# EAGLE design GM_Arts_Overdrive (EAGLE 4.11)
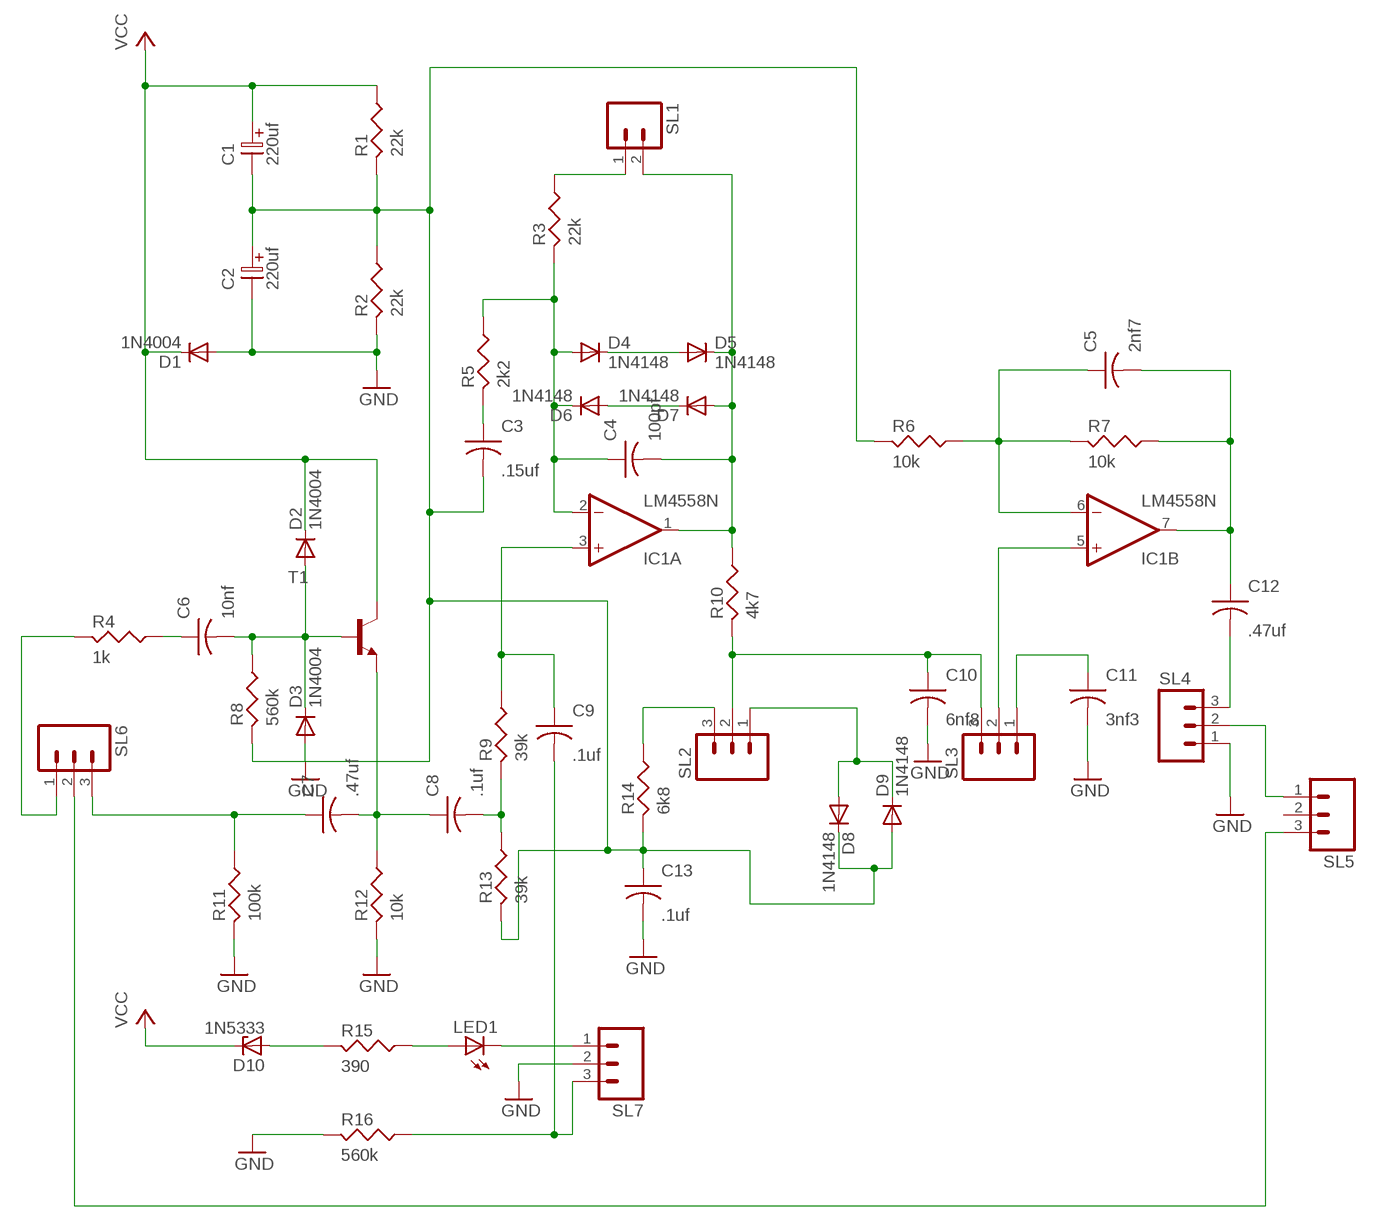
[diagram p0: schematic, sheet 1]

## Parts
C1  220uf  ELC-5L  [ES-5L]
C2  220uf  ELC-5L  [ES-5L]
C3  .15uf  CAP-5  [C-5]
C4  100pf  CAP-5  [C-5]
C5  2nf7  CAP-5  [C-5]
C6  10nf  CAP-5  [C-5]
C7  .47uf  CAP-7,5  [C-7,5]
C8  .1uf  CAP-5  [C-5]
C9  .1uf  CAP-5  [C-5]
C10  6nf8  CAP-7,5  [C-7,5]
C11  3nf3  CAP-5  [C-5]
C12  .47uf  CAP-7,5  [C-7,5]
C13  .1uf  CAP-5  [C-5]
D1  1N4004  [DO41-10]
D2  1N4004  [DO41-10]
D3  1N4004  [DO41-10]
D4  1N4148  [DO35-10]
D5  1N4148  [DO35-10]
D6  1N4148  [DO35-10]
D7  1N4148  [DO35-10]
D8  1N4148  [DO35-10]
D9  1N4148  [DO35-10]
D10  1N5333  [C1702-15]
IC1  LM4558N  [DIL08]
LED1  LED5MM  [LED5MM]
R1  22k  RESUS-12,5  [R-12,5]
R2  22k  RESUS-12,5  [R-12,5]
R3  22k  RESUS-12,5  [R-12,5]
R4  1k  RESUS-12,5  [R-12,5]
R5  2k2  RESUS-12,5  [R-12,5]
R6  10k  RESUS-12,5  [R-12,5]
R7  10k  RESUS-12,5  [R-12,5]
R8  560k  RESUS-12,5  [R-12,5]
R9  39k  RESUS-12,5  [R-12,5]
R10  4k7  RESUS-12,5  [R-12,5]
R11  100k  RESUS-12,5  [R-12,5]
R12  10k  RESUS-12,5  [R-12,5]
R13  39k  RESUS-12,5  [R-12,5]
R14  6k8  RESUS-12,5  [R-12,5]
R15  390  RESUS-12,5  [R-12,5]
R16  560k  RESUS-12,5  [R-12,5]
SL1  M02  [02P]
SL2  M03  [03P]
SL3  M03  [03P]
SL4  M03  [03P]
SL5  M03  [03P]
SL6  M03  [03P]
SL7  M03  [03P]
T1  -NPN-TO92L  [TO92L]

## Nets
GND: C2.2 C10.2 C11.2 C13.2 D1.A D3.A R2.2 R11.2 R12.2 R16.2 SL4.1 SL7.2
N$1: C1.2 C2.1 C3.2 C13.1 D8.C D9.A R1.2 R2.1 R6.2 R8.2 R13.2 R14.2
N$2: C6.1 R4.1
N$3: D10.A R15.2
N$4: LED1.A R15.1
N$5: LED1.K(C) SL7.1
N$6: C6.2 D2.A D3.C R8.1 T1.2(B)
N$7: C7.2 C8.1 R12.1 T1.1(E)
N$8: C7.1 R11.1 SL6.3
N$9: C8.2 R9.2 R13.1
N$10: C9.1 IC1.3(A:+IN) R9.1
N$11: C3.1 R5.2
N$12: C4.1 D4.A D6.C IC1.2(A:-IN) R3.2 R5.1
N$13: D4.C D5.A
N$14: D6.A D7.C
N$15: R3.1 SL1.1
N$16: C4.2 D5.C D7.A IC1.1(A:OUT) R10.1 SL1.2
N$17: C9.2 R16.1 SL7.3
N$18: C10.1 R10.2 SL2.2 SL3.3
N$19: R14.1 SL2.3
N$20: D8.A D9.C SL2.1
N$21: C11.1 SL3.1
N$22: IC1.5(B:+IN) SL3.2
N$23: C12.2 SL4.3
N$24: C5.2 C12.1 IC1.7(B:OUT) R7.1
N$25: SL4.2 SL5.1
N$26: C5.1 IC1.6(B:-IN) R6.1 R7.2
N$27: SL5.3 SL6.2
N$29: R4.2 SL6.1
VCC: C1.1 D1.C D2.C D10.C R1.1 T1.3(C)
Unconnected: SL5.2

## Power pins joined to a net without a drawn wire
V+: IC1.8(P:V+)
V-: IC1.4(P:V-)

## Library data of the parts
C1 C2 = discrete:ELC-5L
C3-C6 C8 C9 C11 C13 = discrete:CAP-5
C7 C10 C12 = discrete:CAP-7,5
D1-D3 = diode:1N4004: DIODE
D4-D9 = diode:1N4148: DIODE
D10 = diode:1N5333: Z DIODE
IC1 = linear:*4558: OP AMP
LED1 = led:LED: LED
R1-R16 = discrete:RESUS-12,5
SL1 = con-amp-quick:M02: AMP QUICK CONNECTOR
SL2-SL7 = con-amp-quick:M03: AMP QUICK CONNECTOR
T1 = transistor:*-NPN-: NPN Transistror

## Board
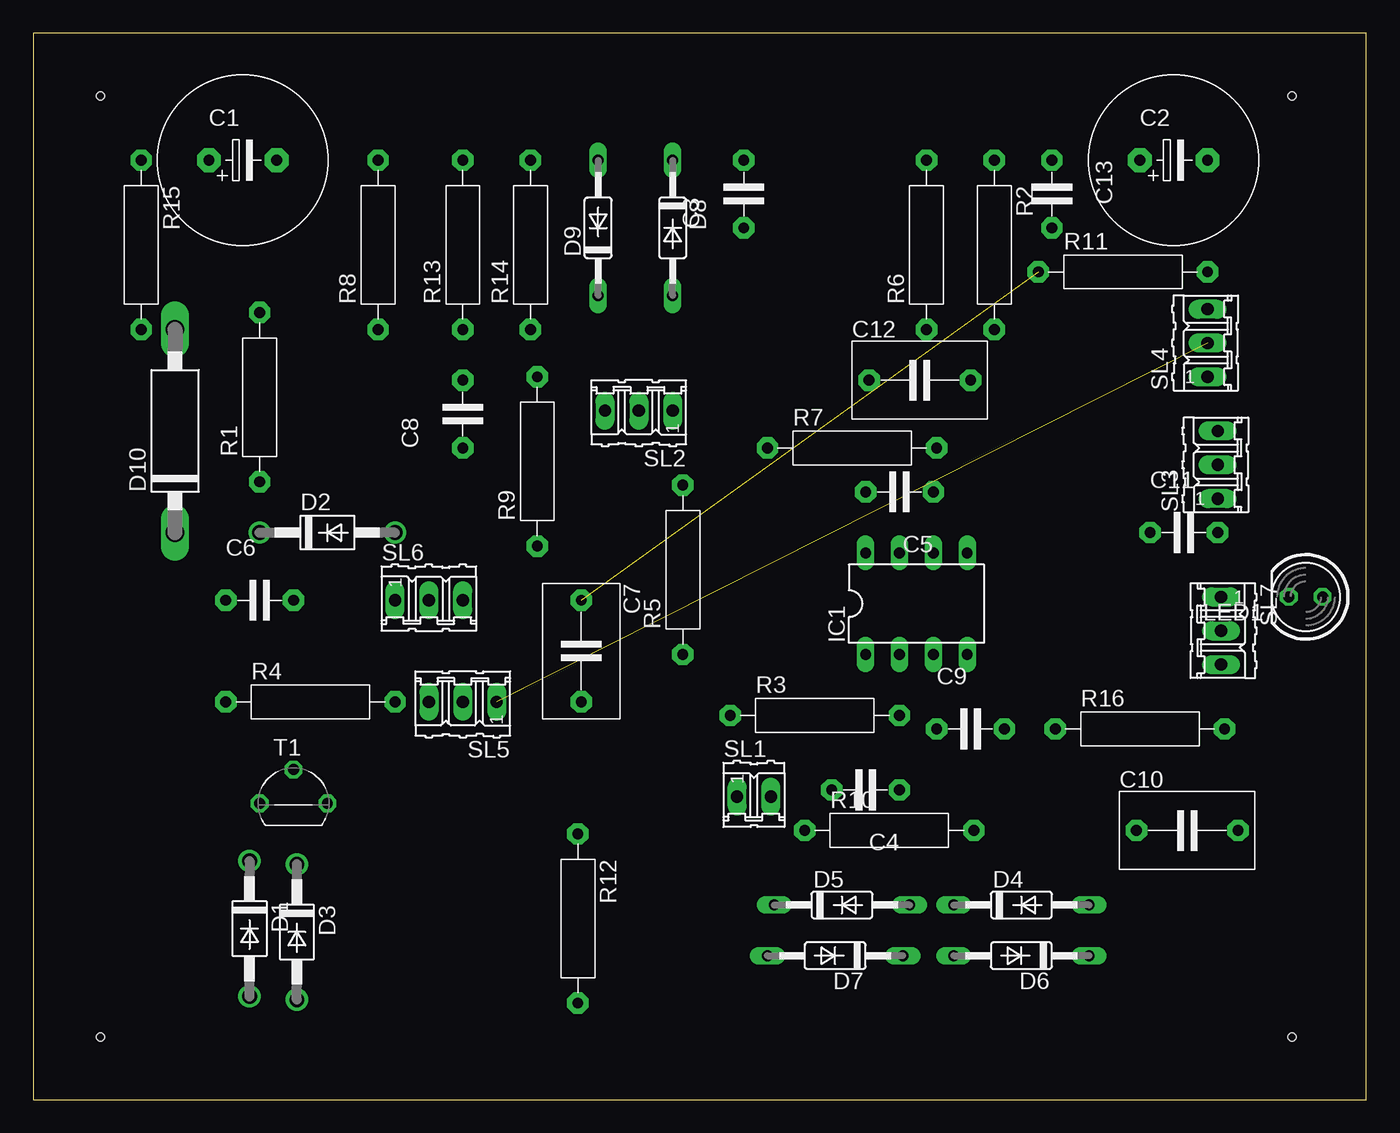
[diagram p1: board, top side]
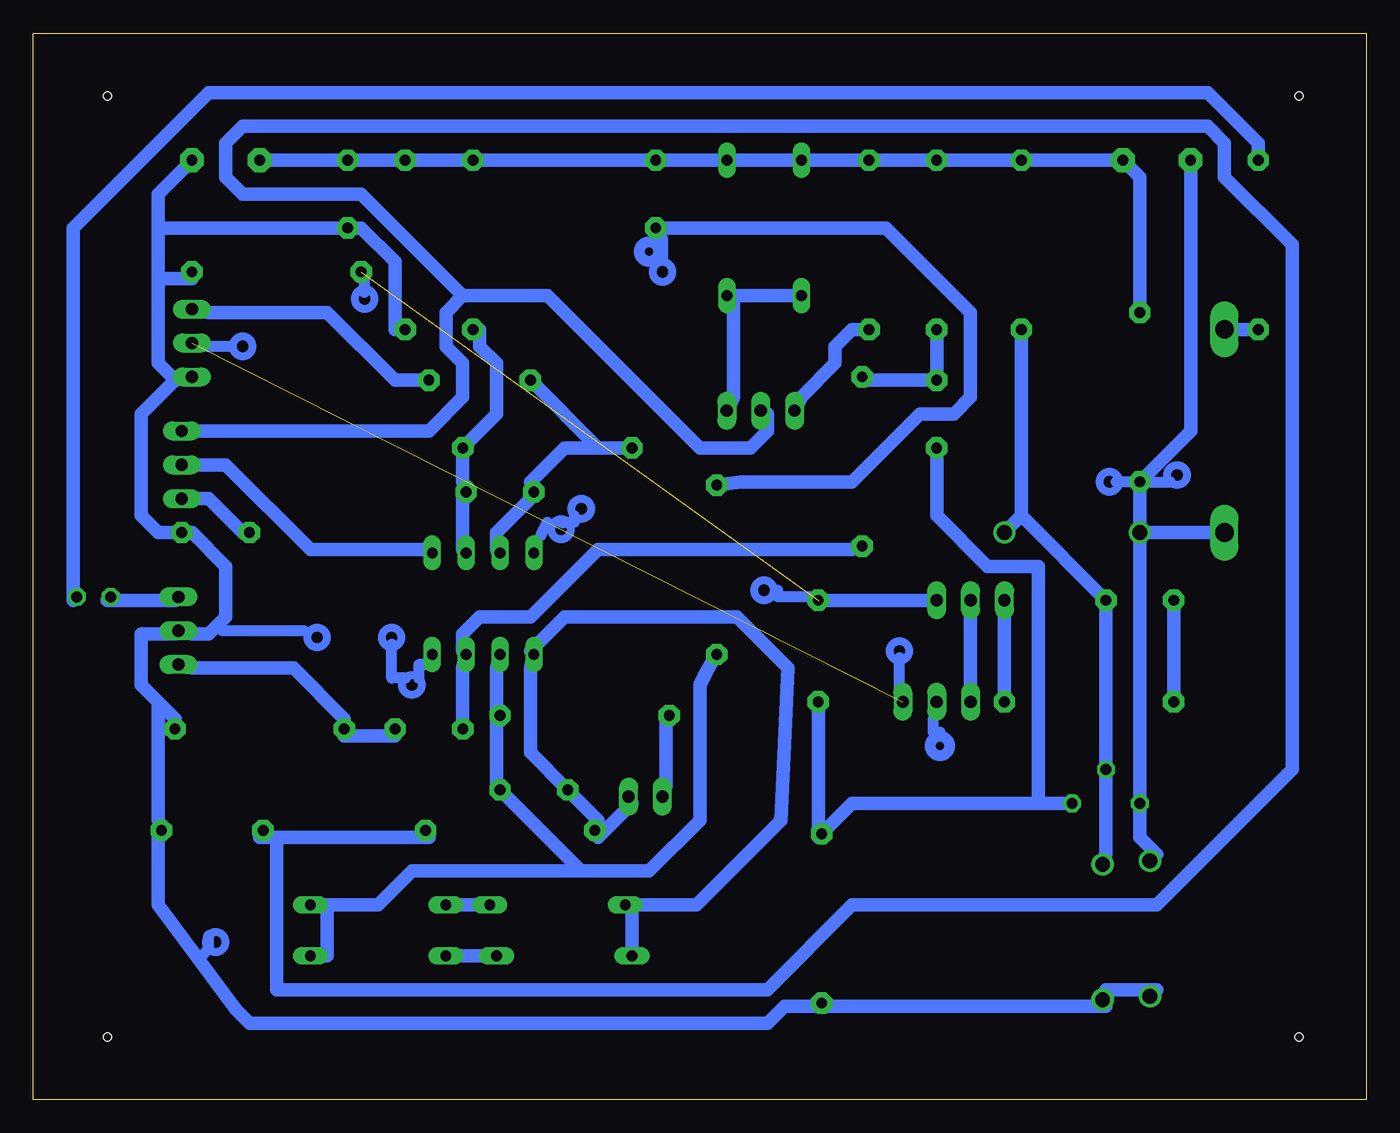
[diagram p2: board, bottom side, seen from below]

Size 100 x 80 mm. Coordinates in mm from the lower left corner, seen from the top.
Outline: 0,0 100,0 100,80 0,80 0,0
Copper layers (1*16): Top 0.035mm / dielectric 1.5mm / Bottom 0.035mm
Design rules "default": minimum track width 40mil, minimum drill 32mil, track to track 20mil, track to pad 20mil, pad to pad 20mil, via to via 8mil, smd to smd 8mil, copper to edge 40mil, drill to drill 8mil, minimum pad ring 10mil, minimum via ring 8mil, stop-mask expansion 4mil, vias tented up to drill 0mil, thermal gap 10mil
Holes 0.61 mm at 5.04,4.69 94.45,4.69 94.45,75.31 5.04,75.31

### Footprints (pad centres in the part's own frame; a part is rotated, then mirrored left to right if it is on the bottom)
ES-5L = drill 0.813 pad 1.778 octagon: 1 0,0; 2 5.08,0
C-5 = drill 0.813 pad 1.6 octagon: 1 -2.54,0; 2 2.54,0
C-7,5 = drill 0.813 pad 1.6 octagon: 1 -3.81,0; 2 3.81,0
DO41-10 = drill 1.118 round: A 5.08,0; C -5.08,0
DO35-10 = drill 0.813 long: A 5.08,0; C -5.08,0
C1702-15 = drill 1.397 long: A 7.62,0; C -7.62,0
DIL08 = drill 0.813 long: 1 -3.81,-3.81; 2 -1.27,-3.81; 3 1.27,-3.81; 4 3.81,-3.81; 5 3.81,3.81; 6 1.27,3.81; 7 -1.27,3.81; 8 -3.81,3.81
LED5MM = drill 0.813 octagon: A -1.27,0; K 1.27,0
R-12,5 = drill 0.813 pad 1.6 octagon: 1 -6.35,0; 2 6.35,0
02P = drill 0.914 long: 1 -1.27,0; 2 1.27,0
03P = drill 0.914 long: 1 -2.54,0; 2 0,0; 3 2.54,0
TO92L = drill 0.813 octagon: 1 2.54,0; 2 0,2.54; 3 -2.54,0

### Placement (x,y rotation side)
C1  13.17,70.48 0 top
C2  83.02,70.48 0 top
C3  53.3,67.94 90 top
C4  62.45,23.24 180 top
C5  64.99,45.59 180 top
C6  16.98,37.46 0 top
C7  41.11,33.65 270 top
C8  32.22,51.43 90 top
C9  70.32,27.81 0 top
C10  86.58,20.19 0 top
C11  86.32,42.54 0 top
C12  66.51,53.97 0 top
C13  76.42,67.94 270 top
D1  16.22,12.82 270 top
D2  22.06,42.54 0 top
D3  19.77,12.57 270 top
D4  74.13,14.6 0 top
D5  60.67,14.6 0 top
D6  74.13,10.79 180 top
D7  60.16,10.79 180 top
D8  47.97,65.4 270 top
D9  42.38,65.4 90 top
D10  10.63,50.16 90 top
IC1  66.26,37.21 0 top
LED1  95.47,37.71 180 top
R1  16.98,52.7 90 top
R2  72.1,64.13 270 top
R3  58.64,28.82 0 top
R4  20.79,29.84 0 top
R5  48.73,39.75 90 top
R6  67.02,64.13 90 top
R7  61.43,48.89 0 top
R8  25.87,64.13 90 top
R9  37.81,47.87 90 top
R10  64.22,20.19 0 top
R11  81.75,62.1 0 top
R12  40.86,13.58 270 top
R13  32.22,64.13 90 top
R14  37.3,64.13 90 top
R15  8.09,64.13 270 top
R16  83.02,27.81 0 top
SL1  54.06,22.73 0 top
SL2  45.43,51.68 180 top
SL3  88.86,47.62 90 top
SL4  88.1,56.76 90 top
SL5  32.22,29.84 180 top
SL6  29.68,37.46 0 top
SL7  89.12,35.17 270 top
T1  19.52,22.22 0 top

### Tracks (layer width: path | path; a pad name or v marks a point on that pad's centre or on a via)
GND
  Bottom 1.016: 41.11,6.98 19.52,6.98 D3.A 19.52,8.25 15.71,8.25 D1.A | 90.64,29.84 89.37,28.57 R16.2 | 90.64,29.84 91.91,31.11 91.91,34.92 89.37,34.92 SL7.2 88.1,34.92 86.83,34.92 85.56,36.19 85.56,40 88.1,42.54 C11.2 90.64,42.54 91.91,43.81 91.91,51.43 89.37,53.97 | 90.64,29.84 90.64,20.95 C10.2 90.64,19.68 90.64,14.6 84.8,6.73 83.78,5.71 44.92,5.71 43.65,6.98 41.11,6.98 | R2.2 72.86,57.78 72.86,62.86 75.4,65.4 C13.2 90.64,65.4 | 89.37,53.97 90.64,55.24 90.64,61.59 | 90.64,65.4 90.64,67.94 C2.2 | 90.64,61.59 90.64,65.4 | 90.64,61.59 88.1,61.59 R11.2 | 89.37,53.97 SL4.1 | 41.11,6.98 R12.2
N$1
  Bottom 1.016: C2.1 76.67,70.48 C13.1 R2.1 R6.2 C3.2 D8.C 47.46,70.48 D9.A R14.2 R13.2 R8.2 C1.2 16.98,69.21 R1.2
N$2
  Bottom 1.016: R4.1 C6.1
N$3
  Bottom 1.016: R15.2 D10.A
N$4
  Bottom 1.016: R15.1 8.09,71.75 11.9,75.56 86.83,75.56 96.99,65.4 96.99,37.46 LED1.A
N$5
  Bottom 1.016: LED1.K 94.45,37.46 89.37,37.46 SL7.1
N$6
  Bottom 1.016: 25.87,43.81 R8.1 | 25.87,43.81 D2.A | D3.C 19.52,18.41 T1.2 C6.2 25.87,43.81
N$7
  Bottom 1.016: 24.6,22.22 38.57,22.22 R12.1 41.11,19.68 C7.2 | T1.1 24.6,22.22 | C8.1 32.22,43.81 28.41,40 24.6,40 24.6,22.22
N$8  (1 unrouted)
  Bottom 1.016: SL6.3 C7.1
N$9
  Bottom 1.016: R13.1 C8.2 37.3,53.97 R9.2
N$10
  Bottom 1.016: C9.1 67.78,32.38 IC1.3 67.78,33.65 67.78,34.92 66.51,36.19 62.7,36.19 57.62,41.27 38.57,41.27 R9.1
N$11
  Bottom 1.016: R5.2 46.95,46.35 38.57,46.35 33.49,51.43 30.95,51.43 29.68,52.7 29.68,59.05 36.03,65.4 C3.1
N$12
  Bottom 1.016: 65.24,28.57 65.24,32.38 IC1.2 | 77.94,14.6 77.94,10.79 D6.C | 58.89,17.14 53.81,17.14 50,20.95 50,31.11 49.49,32.13 R5.1 | 58.89,17.14 C4.1 65.24,23.49 65.24,28.57 | 77.94,14.6 74.13,14.6 71.59,17.14 58.89,17.14 | 77.94,14.6 D4.A | 65.24,28.57 R3.2
N$13
  Bottom 1.016: D5.A D4.C
N$14
  Bottom 1.016: D7.C D6.A
N$15
  Bottom 1.016: SL1.1 52.54,23.49 52.54,28.57 R3.1
N$16
  Bottom 1.016: SL1.2 55.08,22.22 57.62,19.68 R10.1 57.62,20.95 C4.2 62.7,26.03 62.7,32.38 IC1.1 62.7,33.65 60.16,36.19 47.21,36.19 43.4,32.38 43.9,20.95 50.25,14.6 55.08,14.6 | D7.A 55.08,14.6 | 55.08,14.6 D5.C
N$17
  Bottom 1.016: SL7.3 88.1,32.38 80.48,32.38 76.67,28.57 R16.1 76.67,27.3 72.86,27.3 C9.2
N$18
  Bottom 1.016: 81.75,19.68 83.02,19.68 C10.1 | 81.75,19.68 70.32,19.68 R10.2 | 67.78,60.32 69.05,59.05 69.05,56.51 67.78,55.24 67.78,52.7 70.32,50.16 SL3.3 | 67.78,60.32 61.43,60.32 50,48.89 46.19,48.89 44.92,50.16 44.92,51.43 SL2.2 | 81.75,19.68 81.75,8.25 44.92,8.25 38.57,14.6 15.71,14.6 5.55,24.76 5.55,64.13 10.63,69.21 10.63,71.75 11.9,73.02 84.29,73.02 85.56,71.75 85.56,69.21 84.29,67.94 75.4,67.94 67.78,60.32
N$19
  Bottom 1.016: R14.1 38.57,57.78 39.84,56.51 39.84,55.24 42.38,52.7 SL2.3
N$20
  Bottom 1.016: 47.46,60.32 D9.C | 47.46,60.32 47.46,52.7 SL2.1 | 47.46,60.32 D8.A
N$21
  Bottom 1.016: SL3.1 86.83,45.08 84.29,42.54 C11.1
N$22
  Bottom 1.016: IC1.5 70.32,41.27 79.21,41.27 85.56,47.62 SL3.2
N$23
  Bottom 1.016: C12.2 72.86,53.97 77.94,59.05 86.83,59.05 SL4.3
N$24
  Bottom 1.016: IC1.7 65.24,41.27 65.24,42.54 62.7,45.08 C5.2 62.7,46.35 60.16,48.89 57.62,48.89 | 57.62,48.89 R7.1 | 57.62,48.89 C12.1
N$25  (1 unrouted)
N$26
  Bottom 1.016: IC1.6 67.78,41.27 67.78,45.08 C5.1 67.78,46.35 R7.2 65.24,51.43 65.24,55.24 66.51,56.51 66.51,57.78 R6.1
N$27
  Bottom 1.016: SL5.3 SL6.2
N$28
  Bottom 0.813: 52.79,64.64 52.79,63.11
N$29
  Bottom 1.016: R4.2 SL6.1
N$30
  Bottom 0.813: 79.72,35.17 85.81,35.17
N$31
  Bottom 0.813: 70.57,32.63 71.08,32.63 71.08,31.62
N$32
  Bottom 0.813: 72.1,31.62 73.11,31.62 73.11,34.16
N$33
  Bottom 0.813: 61.94,42.29 61.43,43.3
N$34
  Bottom 0.813: 60.41,43.3 59.4,43.3 59.4,43.81
N$35
  Bottom 0.813: 41.62,37.71 44.16,37.71 44.16,38.22
N$36
  Bottom 0.813: 35.01,30.6 35.01,33.14
N$37
  Bottom 0.813: 17.23,46.35 18.76,46.35
N$38
  Bottom 0.813: 16.22,46.35 14.69,46.35
N$39
  Bottom 0.813: 75.15,60.57 75.15,61.59
N$40
  Bottom 0.813: 87.34,10.79 86.83,11.3 86.83,12.31
N$41
  Bottom 0.813: 31.97,27.55 32.47,27.55 32.47,28.57
N$42
  Bottom 0.813: 85.31,56.51 87.34,56.51
VCC
  Bottom 1.016: D1.C 15.71,18.41 16.98,19.68 T1.3 D2.C | D2.C R1.1 13.17,50.16 C1.1 | D2.C D10.C
(copper drawn outside any net)
  shapes: Bottom circle x15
